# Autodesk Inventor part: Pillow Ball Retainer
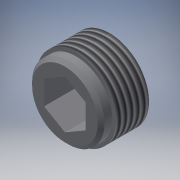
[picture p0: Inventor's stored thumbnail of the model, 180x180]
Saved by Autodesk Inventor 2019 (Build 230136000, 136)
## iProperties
Shininess: 50.0
Compacted: True
Length Units: 11272
Angle Units: 11279
Time Units: 11290
Mass Units: 11286
Length Display Precision: 4
Angle Display Precision: 2
Company: Autodesk
Created: 2000-05
Part Number: Pillow Ball Retainer
Project: Inventor Samples
User Status: IN PROGRESS
Document SubType Name: Modeling
Designer: Autodesk, Inc.
Density: 8.08 g/cm^3
Material: Stainless Steel
Mass: 1.81697 g
Surface Area: 3.29007 cm^2
Volume: 0.224872 cm^3
Appearance: Grey
Density: 0.0
Volumn: 0.0
Area: 0.0
PropertySet Name: Model Information
Control State: 0
Master: False
Checked Out: False
Checked Out Date: 2018-05-30
Last Check In Date: 2018-05-30
Author: Autodesk, Inc.
Revision Number: A
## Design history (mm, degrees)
node "Extrusion1" dims "d0" = 5.08, "d1" = 0
  sketch "Sketch2"
    geometry: C1 r 4.509 at (0, 0)
    constraints: 1 centre point
node "Extrusion2" dims "d3" = 0.635, "d4" = -15 deg
  sketch "Sketch3"
    geometry: C1 r 4.509 at (0, 0) reference; C2 r 3.81 at (0, 0)
    constraints: 1 centre point, 1 concentric
    dimensions: "d2" = 7.62 diameter of C2
node "Extrusion3" dims "d6" = 1.27, "d7" = 0
  sketch "Sketch4"
    geometry: C1 r 4.509 at (0, 0) reference; C2 r 4.128 at (0, 0)
    constraints: 1 centre point, 1 coincident
    dimensions: "d5" = 8.255 diameter of C2
node "Chamfer1" dims "d8" = 0.381, "d9" = 0.381, "d17" = 45 deg
node "Extrusion4" dims "d11" = 3.81, "d12" = 0
  sketch "Sketch5"
    geometry: L1 (-2.381, 1.375)-(-2.381, -1.375); L2 (-2.381, -1.375)-(0, -2.75); L3 (0, -2.75)-(2.381, -1.375); L4 (2.381, -1.375)-(2.381, 1.375); L5 (2.381, 1.375)-(0, 2.75); L6 (0, 2.75)-(-2.381, 1.375); C1 r 3.746 at (0, 0) reference; C2 r 2.381 at (0, 0)
    constraints: 12 end point, 6 tangent, 3 parallel, 2 equal length, 1 centre point, 1 coincident, 1 vertical
    dimensions: "d10" = 4.7625 diameter of C2
node "Extrusion5" dims "d13" = 25.4, "d14" = 0
  sketch "Sketch6"
    geometry: L1 (0, -2.75)-(-2.381, -1.375) reference; L2 (-2.381, -1.375)-(-2.381, 1.375) reference; L3 (-2.381, 1.375)-(0, 2.75) reference; L4 (0, 2.75)-(2.381, 1.375) reference; L5 (2.381, 1.375)-(2.381, -1.375) reference; L6 (2.381, -1.375)-(0, -2.75) reference
thread "Thread1" dims "d15" = 25.4, "d16" = 0
body "Solid1"
